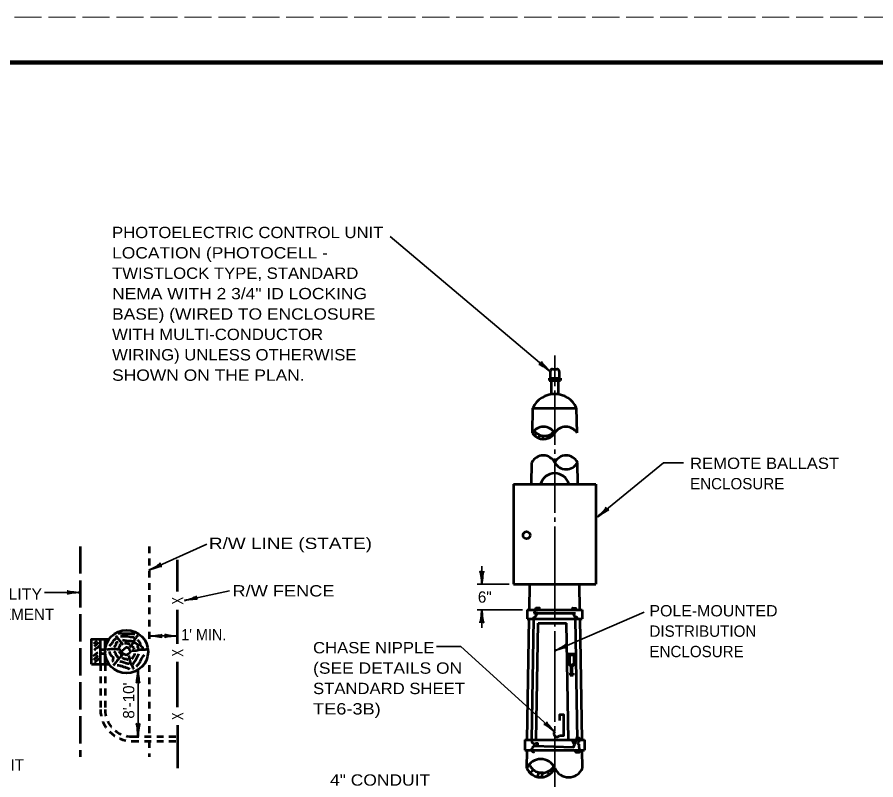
# Model space of a CAD drawing. Extents: x -68 to 612, y -58 to 382.
# Drawn here: x 75.5 to 265, y 213.8 to 382.2 of the extents above; entities that cross this region are included whole.
import ezdxf
from ezdxf.enums import TextEntityAlignment as Align

# ---------------------------------------------------------------- set-up
doc = ezdxf.new("R2010")
doc.units = 0
doc.linetypes.add('LONG_DASHED', pattern=[7.5, 6, -1.5])
doc.linetypes.add('SHORT_DASHED', pattern=[2.7, 1.5, -1.2])
doc.layers.add('1', color=7, linetype='Continuous', lineweight=53)
doc.layers.add('61', color=7, linetype='Continuous', lineweight=35)

msp = doc.modelspace()

# ---------------------------------------------------------------- linework, layer by layer
at = {"layer": '1', "lineweight": 35}
for p, q in [((193.116, 303.972), (157.836, 333.718)), ((194.116, 307.472), (194.116, 302.733)), ((194.116, 301.733), (194.116, 300.733)), ((194.116, 299.733), (194.116, 287.733)), ((194.116, 286.733), (194.116, 285.733)), ((194.116, 284.733), (194.116, 272.733)), ((194.116, 271.733), (194.116, 270.733)), ((194.116, 269.733), (194.116, 249.64)), ((104.625, 260.099), (117.328, 265.79)), ((178.039, 256.97), (178.039, 260.97)), ((184.039, 256.97), (177.039, 256.97)), ((89.375, 255.159), (81.487, 255.159)), ((112.417, 253.4), (122.311, 255.526)), ((187.039, 251.366), (177.039, 251.366)), ((178.039, 251.366), (178.039, 247.366)), ((194.148, 242.28), (213.887, 250.818)), ((194.116, 248.64), (194.116, 247.64)), ((194.116, 246.64), (194.116, 226.64)), ((104.625, 245.555), (110.875, 245.555)), ((173.374, 243.264), (167.997, 243.221)), ((194.13, 224.407), (173.374, 243.264)), ((102.156, 238.072), (102.156, 223.342)), ((194.116, 225.64), (194.116, 224.64)), ((194.116, 223.64), (194.116, 208.64))]:
    msp.add_line(p, q, dxfattribs=at)
at = {"layer": '1'}
for p, q in [((193.116, 303.972), (193.116, 302.472)), ((193.616, 304.472), (194.616, 304.472)), ((195.116, 303.972), (195.116, 302.472)), ((192.866, 302.472), (195.366, 302.472)), ((192.866, 302.472), (192.866, 301.972)), ((192.866, 301.972), (195.366, 301.972)), ((193.366, 301.972), (193.366, 298.919)), ((194.866, 301.972), (194.866, 298.919)), ((195.366, 302.472), (195.366, 301.972)), ((189.188, 290.374), (189.28, 295.873)), ((189.28, 295.873), (198.951, 295.874)), ((199.043, 290.374), (198.951, 295.874)), ((190.117, 290.306), (189.63, 289.83)), ((193.359, 289.566), (193.019, 289.976)), ((193.645, 290.391), (193.94, 290.124)), ((190.586, 289.215), (190.833, 289.893)), ((191.557, 289.718), (191.422, 289.021)), ((192.35, 289.754), (192.694, 289.205)), ((189, 279.078), (189.08, 283.875)), ((199.231, 279.078), (199.151, 283.875)), ((185.039, 279.078), (203.194, 279.078)), ((185.039, 279.078), (185.039, 256.97)), ((203.194, 279.078), (203.194, 256.97)), ((110.875, 255.342), (110.875, 262.342)), ((185.039, 256.97), (203.194, 256.97)), ((188.539, 251.366), (188.632, 256.97)), ((199.694, 251.366), (199.6, 256.97)), ((110.875, 243.842), (110.875, 251.342)), ((188.039, 251.366), (200.194, 251.366)), ((188.039, 251.366), (188.039, 249.366)), ((189.539, 250.616), (198.694, 250.616)), ((200.194, 251.366), (200.194, 249.366)), ((188.039, 249.366), (200.194, 249.366)), ((188.06, 222.616), (188.505, 249.366)), ((189.06, 222.616), (189.505, 249.366)), ((190.059, 222.599), (190.489, 248.366)), ((190.489, 248.366), (196.743, 248.366)), ((197.173, 222.582), (196.743, 248.366)), ((199.172, 222.616), (198.727, 249.366)), ((200.173, 222.616), (199.727, 249.366)), ((93.875, 239.342), (93.875, 244.842)), ((94.875, 239.342), (94.875, 244.842)), ((197.174, 241.627), (198.524, 241.627)), ((197.174, 241.627), (197.174, 239.377)), ((197.399, 241.402), (198.299, 241.402)), ((197.399, 241.402), (197.399, 239.47)), ((198.299, 241.402), (198.299, 239.47)), ((198.524, 241.627), (198.524, 239.377)), ((91.875, 239.342), (95.752, 239.342)), ((110.875, 229.842), (110.875, 239.842)), ((197.174, 239.377), (197.737, 238.815)), ((197.399, 239.47), (197.849, 239.02)), ((197.737, 237.352), (197.737, 238.815)), ((197.849, 239.02), (198.299, 239.47)), ((197.962, 238.815), (198.524, 239.377)), ((197.962, 237.352), (197.962, 238.815)), ((197.512, 237.352), (198.187, 237.352)), ((197.512, 237.352), (197.512, 236.902)), ((197.512, 236.902), (198.187, 236.902)), ((198.187, 237.352), (198.187, 236.902)), ((110.875, 225.842), (110.875, 216.342)), ((187.522, 222.616), (200.71, 222.616)), ((187.522, 222.616), (187.522, 220.366)), ((198.457, 221.497), (198.912, 222.634)), ((200.71, 222.616), (200.71, 220.366)), ((187.522, 220.366), (200.71, 220.366)), ((187.955, 216.366), (188.022, 220.366)), ((199.452, 221.656), (199.537, 220.133)), ((200.277, 216.366), (200.21, 220.366)), ((188.752, 215.259), (189.39, 216.025)), ((190.577, 215.435), (190.231, 214.466)), ((192.946, 214.961), (192.476, 215.588)), ((192.946, 214.961), (192.476, 215.588)), ((192.946, 214.961), (192.476, 215.588)), ((192.946, 214.961), (192.476, 215.588)), ((193.161, 215.957), (193.64, 215.597))]:
    msp.add_line(p, q, dxfattribs=at)
at = {"layer": '1', "linetype": 'LONG_DASHED'}
msp.add_line((89.375, 265.342), (89.375, 218.842), dxfattribs=at)
at = {"layer": '1', "linetype": 'SHORT_DASHED'}
for p, q in [((104.625, 265.342), (104.625, 244.081)), ((93.875, 239.342), (93.875, 229.342)), ((94.875, 239.342), (94.875, 229.342)), ((104.625, 239.127), (104.625, 223.342)), ((100.875, 223.342), (110.875, 223.342)), ((100.875, 222.342), (110.875, 222.342)), ((104.625, 222.342), (104.625, 218.842))]:
    msp.add_line(p, q, dxfattribs=at)
at = {"layer": '1', "lineweight": 13}
msp.add_line((196.866, 222.64), (193.116, 222.64), dxfattribs=at)
at = {"layer": '1', "lineweight": 35}
msp.add_lwpolyline([(203.554, 271.87), (218.114, 283.749), (222.536, 283.749)], dxfattribs=at)
at = {"layer": '1'}
for points in [[(189.505, 249.366), (189.418, 249.602), (189.789, 249.787), (190.319, 250.623), (189.67, 250.623), (189.802, 251.245), (190.001, 251.789), (190.769, 251.776), (190.518, 251.378)], [(198.017, 251.378), (198.11, 251.802), (198.759, 251.723), (198.693, 251.418)], [(198.727, 249.366), (199.13, 249.443), (199.024, 249.734), (198.627, 249.695), (198.097, 250.596)], [(91.875, 239.342), (91.875, 244.842), (95.752, 244.842)], [(195.155, 223.616), (196.155, 223.616), (196.155, 228.116), (195.155, 228.116), (195.155, 226.866)], [(189.06, 222.616), (189.081, 222.123), (189.592, 221.706), (189.554, 221.27), (198.249, 221.024), (198.457, 221.497), (197.946, 222.596)], [(198.912, 222.634), (199.044, 223.184), (199.518, 223.089), (199.442, 222.142)], [(191.189, 214.372), (191.563, 215.344), (190.577, 215.435)], [(192.946, 214.961), (192.476, 215.588), (193.161, 215.957)]]:
    msp.add_lwpolyline(points, dxfattribs=at)
for centre, radius in [((187.908, 267.802), 0.785), ((99.625, 242.092), 4.75), ((94.375, 242.092), 0.5)]:
    msp.add_circle(centre, radius, dxfattribs=at)
for centre, radius, start, end in [((193.616, 303.972), 0.5, 90, 180), ((194.616, 303.972), 0.5, 0, 90), ((194.116, 293.649), 5.323, 24.70337, 155.29762), ((191.652, 288.827), 2.909, 32.12603, 147.87591), ((191.652, 288.827), 2.909, 135.28632, 147.87591), ((191.652, 291.921), 2.909, 212.12419, 248.50023), ((191.652, 291.921), 2.909, 212.12409, 225.97386), ((191.83, 292.446), 2.741, 214.99106, 264.27121), ((191.83, 292.446), 2.741, 214.99106, 231.31632), ((191.83, 292.446), 2.741, 264.27128, 295.69699), ((191.83, 292.446), 2.741, 280.91416, 295.69709), ((191.652, 291.921), 2.909, 290.98858, 321.84618), ((191.83, 292.446), 2.741, 295.69709, 319.35845), ((191.83, 292.446), 2.741, 311.43068, 319.35845), ((191.652, 288.827), 2.909, 32.12603, 39.06319), ((191.652, 291.921), 2.909, 321.84618, 327.87397), ((196.579, 288.827), 2.909, 32.12603, 147.87591), ((191.652, 291.921), 2.909, 248.50024, 290.98876), ((191.652, 291.921), 2.909, 248.50023, 265.46761), ((191.83, 292.446), 2.741, 248.66508, 264.27128), ((191.652, 291.921), 2.909, 290.98876, 305.93139), ((191.598, 282.561), 2.84, 27.5646, 152.44109), ((196.634, 282.561), 2.84, 27.5646, 152.44109), ((196.634, 285.189), 2.84, 207.55891, 332.4354), ((194.116, 278.253), 3.223, 14.84165, 165.15835), ((194.58, 223.93), 0.656, 133.35439, 331.33852), ((191.036, 214.989), 3.374, 24.07948, 155.9231), ((191.036, 214.989), 3.374, 138.90512, 155.92052), ((191.036, 217.742), 3.374, 204.07948, 272.59979), ((191.036, 217.742), 3.374, 204.07948, 227.39786), ((191.319, 218.419), 3.075, 203.21853, 231.14333), ((191.319, 218.419), 3.075, 231.14333, 256.04211), ((191.319, 218.419), 3.075, 306.79311, 327.33243), ((191.036, 217.742), 3.374, 320.52562, 335.92052), ((197.196, 217.742), 3.374, 204.07948, 335.92052), ((191.036, 217.742), 3.374, 256.20747, 272.59984), ((191.319, 218.419), 3.075, 256.04211, 274.61107), ((191.036, 217.742), 3.374, 272.59984, 320.52559), ((191.319, 218.419), 3.075, 274.61107, 292.29814), ((191.319, 218.419), 3.075, 292.29814, 306.79311), ((191.036, 217.742), 3.374, 304.47948, 320.52562)]:
    msp.add_arc(centre, radius, start, end, dxfattribs=at)
at = {"layer": '1', "linetype": 'SHORT_DASHED'}
for radius in [7, 6]:
    msp.add_arc((100.875, 229.342), radius, 180, 270, dxfattribs=at)
at = {"layer": '1', "lineweight": 40}
for centre, major_axis, ratio, start_param, end_param in [((192.104, 304.464), (1.466, -1.032), 0.122415, 0.8963533, 3.1415927), ((192.396, 304.856), (1.23, -1.266), 0.07063, 3.1407148, 5.41811), ((204.225, 272.774), (-1.285, -1.25), 0.122415, 0.8963533, 3.1415927), ((204.556, 272.415), (-1.472, -0.974), 0.07063, 3.1407148, 5.41811), ((105.508, 260.797), (-1.566, -0.873), 0.122415, 0.8963533, 3.1415927), ((105.508, 260.797), (-1.566, -0.873), 0.122415, 0.8963533, 3.1415927), ((105.734, 260.364), (-1.675, -0.558), 0.07063, 3.1407148, 5.41811), ((105.734, 260.364), (-1.675, -0.558), 0.07063, 3.1407148, 5.41811), ((177.762, 258.061), (0.156, -1.786), 0.122415, 0.8963533, 3.1415927), ((177.762, 258.061), (0.156, -1.786), 0.122415, 0.8963533, 3.1415927), ((178.25, 258.09), (-0.176, -1.756), 0.07063, 3.1407148, 5.41811), ((178.25, 258.09), (-0.176, -1.756), 0.07063, 3.1407148, 5.41811), ((88.284, 254.883), (1.786, 0.156), 0.122415, 0.8963533, 3.1415927), ((88.284, 254.883), (1.786, 0.156), 0.122415, 0.8963533, 3.1415927), ((88.254, 255.371), (1.756, -0.176), 0.07063, 3.1407148, 5.41811), ((88.254, 255.371), (1.756, -0.176), 0.07063, 3.1407148, 5.41811), ((113.426, 253.899), (-1.713, -0.528), 0.122415, 0.8963533, 3.1415927), ((113.426, 253.899), (-1.713, -0.528), 0.122415, 0.8963533, 3.1415927), ((113.557, 253.428), (-1.754, -0.197), 0.07063, 3.1407148, 5.41811), ((113.557, 253.428), (-1.754, -0.197), 0.07063, 3.1407148, 5.41811), ((177.827, 250.245), (0.176, 1.756), 0.07063, 3.1407148, 5.41811), ((178.315, 250.274), (-0.156, 1.786), 0.122415, 0.8963533, 3.1415927), ((105.716, 245.831), (-1.786, -0.156), 0.122415, 0.8963533, 3.1415927), ((105.716, 245.831), (-1.786, -0.156), 0.122415, 0.8963533, 3.1415927), ((105.746, 245.343), (-1.756, 0.176), 0.07063, 3.1407148, 5.41811), ((105.746, 245.343), (-1.756, 0.176), 0.07063, 3.1407148, 5.41811), ((109.784, 245.279), (1.786, 0.156), 0.122415, 0.8963533, 3.1415927), ((109.784, 245.279), (1.786, 0.156), 0.122415, 0.8963533, 3.1415927), ((109.754, 245.767), (1.756, -0.176), 0.07063, 3.1407148, 5.41811), ((109.754, 245.767), (1.756, -0.176), 0.07063, 3.1407148, 5.41811), ((195.04, 242.967), (-1.577, -0.852), 0.122415, 0.8963533, 3.1415927), ((195.26, 242.53), (1.682, 0.536), 0.07063, 6.2823074, 8.5597026), ((101.945, 236.952), (0.176, 1.756), 0.07063, 3.1407148, 5.41811), ((101.945, 236.952), (0.176, 1.756), 0.07063, 3.1407148, 5.41811), ((102.433, 236.981), (-0.156, 1.786), 0.122415, 0.8963533, 3.1415927), ((102.433, 236.981), (-0.156, 1.786), 0.122415, 0.8963533, 3.1415927), ((101.88, 224.433), (0.156, -1.786), 0.122415, 0.8963533, 3.1415927), ((102.368, 224.462), (-0.176, -1.756), 0.07063, 3.1407148, 5.41811), ((193.136, 224.936), (1.427, -1.085), 0.122415, 0.8963533, 3.1415927), ((193.443, 225.317), (-1.182, 1.311), 0.07063, 6.2823074, 8.5597026)]:
    msp.add_ellipse(centre, major_axis=major_axis, ratio=ratio, start_param=start_param, end_param=end_param, dxfattribs=at)
at = {"layer": '1'}
for points in [[(95.879, 243.403), (96.636, 244.235), (96.919, 244.681), (97.439, 245.067)], [(98.91, 243.626), (98.152, 244.517), (97.736, 245.008), (97.349, 245.632)], [(97.81, 246.153), (98.91, 246.138), (99.593, 246.138), (100.544, 246.093), (101.48, 245.989)], [(98.286, 245.543), (99.236, 245.484), (99.861, 245.513), (100.485, 245.394), (101.079, 245.275), (101.361, 245.186)], [(98.716, 244.711), (99.549, 244.547), (100.188, 244.473), (100.663, 244.473), (101.034, 244.413)], [(100.381, 243.18), (100.871, 243.685), (101.138, 244.235), (101.51, 244.844), (102.06, 245.602), (102.164, 245.721)], [(102.06, 244.785), (102.387, 244.265), (102.624, 243.73), (102.669, 243.507), (103.055, 243.135), (103.144, 242.719)], [(93.1, 244.399), (92.714, 244.131), (92.357, 243.789)], [(93.516, 244.012), (93.1, 243.745), (92.847, 243.566), (92.476, 243.224)], [(93.665, 243.418), (93.293, 243.031), (92.996, 242.868), (92.595, 242.541), (92.476, 242.362)], [(98.39, 242.451), (97.305, 242.615), (95.893, 242.585), (95.299, 242.511)], [(96.904, 243.18), (97.305, 243.685), (97.424, 244.101), (97.78, 244.28)], [(97.825, 242.927), (98.152, 243.254), (98.256, 243.641), (98.33, 243.73)], [(99.177, 243.997), (99.742, 243.938), (100.143, 243.819), (100.41, 243.789), (100.44, 243.789)], [(100.797, 242.347), (101.733, 242.377), (102.372, 242.511), (103.219, 242.57), (103.739, 242.6), (104.11, 242.63)], [(100.99, 243.299), (101.124, 242.942), (101.287, 242.749)], [(101.391, 244.086), (102.104, 243.492), (102.045, 243.15), (102.178, 242.942), (102.253, 242.778)], [(93.323, 241.946), (92.892, 241.619), (92.624, 241.366), (92.283, 241.084)], [(93.367, 241.188), (92.996, 240.876), (92.699, 240.594), (92.476, 240.385), (92.372, 240.311)], [(95.849, 242.11), (96.176, 241.292), (96.592, 240.921), (96.592, 240.385), (96.577, 240.044), (96.651, 239.954)], [(98.791, 241.426), (98.003, 240.638), (97.186, 239.657), (96.696, 239.018)], [(96.815, 242.184), (97.156, 241.768), (97.275, 241.426), (97.587, 241.114), (97.632, 240.906), (97.647, 240.831), (97.676, 240.802)], [(97.944, 242.169), (98.137, 241.901), (98.345, 241.693), (98.404, 241.411), (98.404, 241.366)], [(98.657, 240.772), (99.162, 240.549), (99.563, 240.504), (99.831, 240.4), (99.979, 240.326)], [(100.024, 241.218), (100.306, 240.385), (100.678, 239.226), (100.871, 238.973), (101.034, 238.483), (101.242, 238.275)], [(101.406, 241.708), (101.138, 241.025), (101.005, 240.846), (100.901, 240.608), (100.767, 240.415)], [(102.283, 241.589), (101.971, 240.935), (101.673, 240.371), (101.302, 239.746), (100.945, 239.167), (100.945, 239.152)], [(103.531, 241.366), (102.877, 240.489), (102.654, 240.029), (102.238, 239.33), (101.822, 238.84), (101.777, 238.75)], [(93.486, 240.623), (93.055, 240.103), (92.862, 239.984), (92.714, 239.806), (92.595, 239.702)], [(97.572, 239.122), (98.167, 239.033), (98.806, 238.825), (99.504, 238.617), (100.054, 238.394), (100.306, 238.26)], [(98.152, 239.969), (98.954, 239.776), (99.474, 239.568), (99.905, 239.494), (100.217, 239.464)], [(189.592, 221.706), (190.293, 221.876), (190.217, 221.289)], [(199.442, 222.142), (199.177, 221.876), (199.461, 221.649)], [(189.554, 221.27), (189.441, 221.194), (189.138, 220.853), (189.005, 220.474), (189.1, 220.209), (189.346, 219.963), (189.649, 220.057)], [(199.537, 220.133), (199.499, 219.868), (199.158, 219.83), (198.836, 219.849), (198.684, 220.019), (198.628, 220.36)]]:
    msp.add_spline(points, degree=3, dxfattribs=at)
at = {"layer": '1', "linetype": 'LONG_DASHED'}
msp.add_spline([(99.638, 243.12), (99.816, 243.031), (100.113, 242.897), (100.232, 242.689), (100.291, 242.362), (100.47, 242.169), (100.395, 242.02), (100.351, 241.901), (100.188, 241.679), (99.846, 241.47), (99.504, 241.352), (99.236, 241.441), (98.806, 241.738), (98.598, 242.02), (98.627, 242.258), (98.88, 242.481), (99.103, 242.645), (99.37, 242.942), (99.593, 243.076)], degree=3, dxfattribs=at)
at = {"layer": '61', "linetype": 'LONG_DASHED', "lineweight": 13}
msp.add_line((-67.611, 382.166), (612.409, 382.166), dxfattribs=at)
at = {"layer": '61', "lineweight": 158}
msp.add_lwpolyline([(601.429, 372.166), (-37.611, 372.166), (-37.611, -47.854)], dxfattribs=at)

# ---------------------------------------------------------------- texts
at = {"layer": '1'}
for s, width, p in [('PHOTOELECTRIC CONTROL UNIT', 1.1, (96.433, 333.39)), ('LOCATION (PHOTOCELL -', 1.15, (96.433, 328.89)), ('TWISTLOCK TYPE, STANDARD', 1.1, (96.433, 324.39)), ('NEMA WITH 2 3/4" ID LOCKING', 1.15, (96.433, 319.89)), ('BASE) (WIRED TO ENCLOSURE', 1.15, (96.433, 315.39)), ('WITH MULTI-CONDUCTOR', 1.1, (96.433, 310.89)), ('WIRING) UNLESS OTHERWISE', 1.1, (96.433, 306.39)), ('SHOWN ON THE PLAN.', 1.15, (96.433, 301.89)), ('REMOTE BALLAST', 1.1, (223.983, 282.428)), ('POLE-MOUNTED', 1.05, (215.019, 249.877)), ('CHASE NIPPLE', 1.1, (140.786, 241.724)), ('(SEE DETAILS ON', 1.15, (140.786, 237.224)), ('STANDARD SHEET', 1.1, (140.786, 232.724)), ('TE6-3B)', 1.2, (140.786, 228.224)), ('4" CONDUIT', 1.15, (144.532, 212.513))]:
    msp.add_text(s, height=2.5, dxfattribs=dict(at, width=width)).set_placement(p)
for s, p in [('ENCLOSURE', (223.983, 277.928)), ('DISTRIBUTION', (215.019, 245.377)), ('ENCLOSURE', (215.019, 240.877)), ('CONDUIT', (61.752, 215.86))]:
    msp.add_text(s, height=2.5, dxfattribs=at).set_placement(p)
for s, width, p in [('R/W LINE (STATE)', 1.25, (135.797, 264.76)), ('UTILITY', 1.05, (74.452, 253.593)), ('R/W FENCE', 1.2, (134.258, 254.276)), ("1' MIN.", 0.95, (116.668, 244.598))]:
    msp.add_text(s, height=2.5, dxfattribs=dict(at, width=width)).set_placement(p, align=Align.CENTER)
at = {"layer": '1', "width": 0.75}
for p in [(112.125, 253.342), (112.125, 241.842), (112.125, 227.842)]:
    msp.add_text('X', height=2.5, rotation=90, dxfattribs=at).set_placement(p, align=Align.CENTER)
at = {"layer": '1'}
for s, p in [('6"', (178.678, 252.909)), ('6"', (178.678, 252.909)), ('EASEMENT', (74.452, 249.093))]:
    msp.add_text(s, height=2.5, dxfattribs=at).set_placement(p, align=Align.CENTER)
msp.add_text("8'-10'", height=2.5, rotation=90, dxfattribs=at).set_placement((101.344, 231.29), align=Align.CENTER)

doc.saveas('drawing.dxf')
